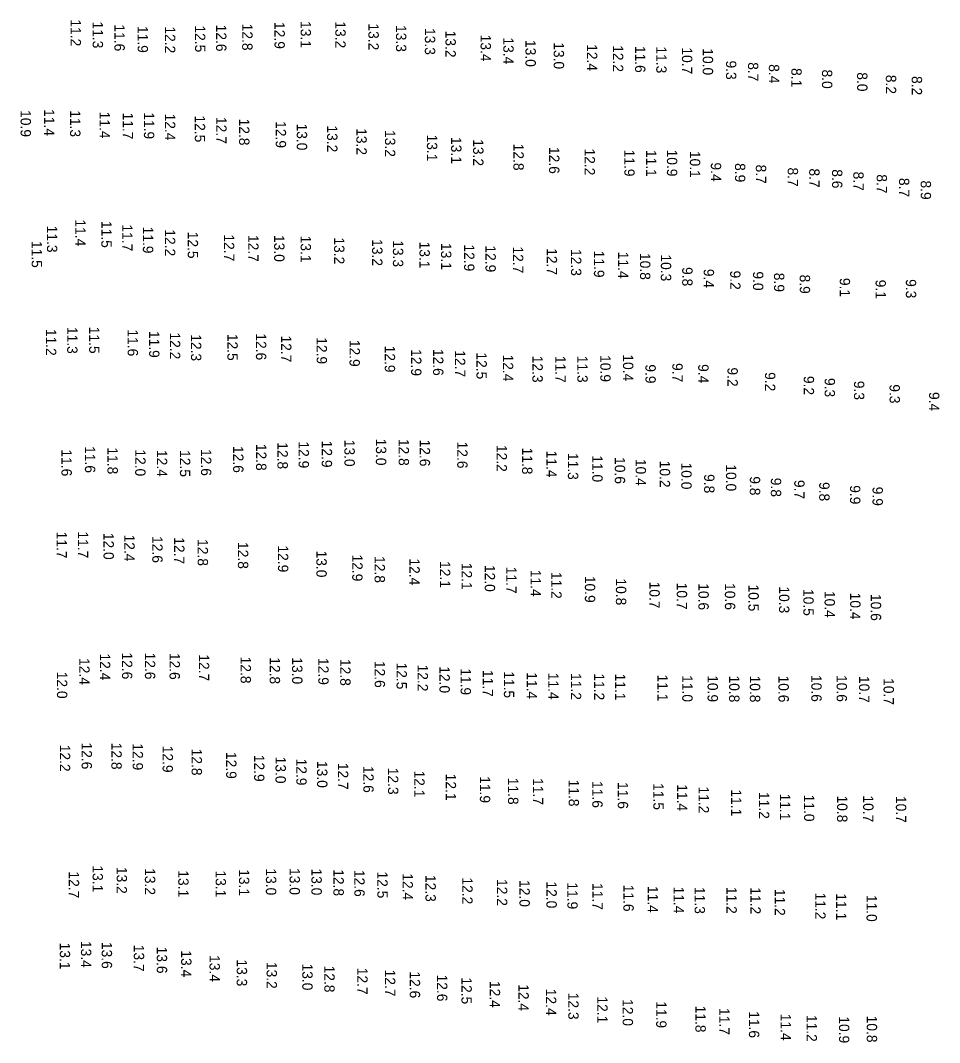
# Model space of a CAD drawing. Extents: x 988130 to 1132882, y 654656 to 841453.
# Drawn here: x 1112009.9 to 1112454.6, y 656908.8 to 657403.6 of the extents above; entities that cross this region are included whole.
import ezdxf

# ---------------------------------------------------------------- set-up
doc = ezdxf.new("R2010")
doc.units = 0
doc.layers.add('V-TOPO-SOUN', color=7, linetype='Continuous')

msp = doc.modelspace()

# ---------------------------------------------------------------- texts
at = {"layer": 'V-TOPO-SOUN'}
for s, p in [('11.2 ', (1112034.21, 657404.08)), ('11.3 ', (1112044.89, 657403.06)), ('11.6 ', (1112055.4, 657401.66)), ('11.9 ', (1112066.64, 657400.9)), ('12.5 ', (1112094.38, 657401.15)), ('12.6 ', (1112104.59, 657401.54)), ('12.8 ', (1112117.22, 657402)), ('12.9 ', (1112132.84, 657402.81)), ('13.1 ', (1112145.49, 657403.25)), ('13.2 ', (1112162.28, 657403.13)), ('13.2 ', (1112178.29, 657402.13)), ('13.3 ', (1112191.62, 657401.33)), ('12.2 ', (1112079.87, 657400.69)), ('13.3 ', (1112205.58, 657399.89)), ('13.2 ', (1112215.56, 657398.63)), ('13.4 ', (1112232.55, 657396.68)), ('13.4 ', (1112243.55, 657395.34)), ('13.0 ', (1112254.26, 657394.1)), ('13.0 ', (1112267.93, 657393.02)), ('12.4 ', (1112283.98, 657392.09)), ('12.2 ', (1112296.56, 657391.61)), ('11.6 ', (1112307.28, 657391.26)), ('11.3 ', (1112317.53, 657390.98)), ('10.7 ', (1112329.96, 657390.53)), ('10.0 ', (1112340.02, 657390.08)), ('9.3', (1112351.27, 657384.17)), ('8.7', (1112361.92, 657383.35)), ('8.4', (1112372.01, 657382.39)), ('8.1', (1112382.89, 657380.52)), ('8.0', (1112397.71, 657379.81)), ('8.0', (1112414.71, 657378.48)), ('8.2', (1112428.61, 657377.24)), ('8.2', (1112441.13, 657376.65)), ('10.9 ', (1112010.01, 657360.16)), ('11.4 ', (1112021.41, 657360.64)), ('11.3 ', (1112033.97, 657360.12)), ('11.4 ', (1112048.21, 657359.42)), ('11.7 ', (1112059.46, 657358.98)), ('11.9 ', (1112069.68, 657359.12)), ('12.4 ', (1112079.85, 657358.5)), ('12.5 ', (1112094.3, 657357.58)), ('12.7 ', (1112104.65, 657356.84)), ('12.8 ', (1112115.72, 657356.05)), ('12.9 ', (1112133.45, 657354.83)), ('13.0 ', (1112143.64, 657353.68)), ('13.2 ', (1112158.3, 657352.76)), ('13.2 ', (1112172.46, 657351.42)), ('13.2 ', (1112186.3, 657350.51)), ('13.1 ', (1112206.58, 657348.34)), ('13.1 ', (1112218.3, 657347.14)), ('13.2 ', (1112228.94, 657346.1)), ('12.8 ', (1112248.42, 657343.91)), ('12.6 ', (1112265.68, 657342.33)), ('12.2 ', (1112282.87, 657341.58)), ('11.9 ', (1112302.09, 657341.04)), ('11.1 ', (1112312.64, 657340.9)), ('10.9 ', (1112322.7, 657341.05)), ('10.1 ', (1112333.8, 657340.42)), ('9.4', (1112343.95, 657334.82)), ('8.9', (1112355.62, 657334.52)), ('8.7', (1112365.71, 657333.79)), ('8.7', (1112381.14, 657332.39)), ('8.7', (1112391.54, 657331.93)), ('8.6', (1112402.58, 657331.54)), ('8.7', (1112412.86, 657330.41)), ('8.7', (1112424.18, 657329.1)), ('8.7', (1112434.96, 657327.34)), ('8.9', (1112445.47, 657326.11)), ('11.4 ', (1112036.47, 657307.26)), ('11.3 ', (1112022.77, 657304.23)), ('11.5 ', (1112049.09, 657306.5)), ('11.7 ', (1112059.15, 657304.83)), ('11.9 ', (1112069.17, 657303.77)), ('12.2 ', (1112079.83, 657302.46)), ('12.5 ', (1112090.88, 657301.3)), ('12.7 ', (1112108.39, 657300)), ('12.7 ', (1112120.11, 657299.74)), ('13.0 ', (1112132.67, 657299.72)), ('13.1 ', (1112145.49, 657299.41)), ('13.2 ', (1112161.67, 657298.55)), ('13.2 ', (1112180.08, 657297.71)), ('13.3 ', (1112190.13, 657297.2)), ('11.5 ', (1112015.36, 657296.86)), ('13.1 ', (1112202.98, 657296.53)), ('13.1 ', (1112213.42, 657295.84)), ('12.9 ', (1112224.55, 657295.16)), ('12.9 ', (1112234.91, 657294.69)), ('12.7 ', (1112248.21, 657294.17)), ('12.7 ', (1112264.55, 657293.32)), ('12.3 ', (1112276.3, 657292.91)), ('11.9 ', (1112287.38, 657292.12)), ('11.4 ', (1112299.06, 657291.63)), ('10.8 ', (1112309.68, 657291)), ('10.3 ', (1112319.75, 657290.33)), ('9.8', (1112330.1, 657284.19)), ('9.4', (1112340.5, 657283.34)), ('9.2', (1112353.29, 657282.5)), ('9.0', (1112364.34, 657282.1)), ('8.9', (1112374.5, 657281.43)), ('8.9', (1112386.96, 657280.54)), ('9.1', (1112406.3, 657278.95)), ('9.1', (1112423.63, 657278.09)), ('9.3', (1112438.28, 657278.34)), ('11.2 ', (1112022.27, 657254.29)), ('11.3 ', (1112032.54, 657255.22)), ('11.5 ', (1112043.18, 657255.3)), ('11.6 ', (1112061.82, 657254.01)), ('11.9 ', (1112072.18, 657253.29)), ('12.2 ', (1112082.25, 657252.54)), ('12.3 ', (1112092.45, 657251.67)), ('12.5 ', (1112110.05, 657251.86)), ('12.6 ', (1112123.86, 657252.11)), ('12.7 ', (1112136.03, 657251.07)), ('12.9 ', (1112153.24, 657250.23)), ('12.9 ', (1112169.14, 657248.97)), ('12.9 ', (1112186.19, 657246.17)), ('12.9 ', (1112198.94, 657244.47)), ('12.6 ', (1112209.56, 657244.59)), ('12.7 ', (1112220.17, 657243.92)), ('12.5 ', (1112230.56, 657242.89)), ('12.4 ', (1112243.33, 657241.85)), ('12.3 ', (1112257.62, 657241.29)), ('11.7 ', (1112268.72, 657241.23)), ('11.3 ', (1112279.37, 657241.25)), ('10.9 ', (1112290.47, 657241.58)), ('10.4 ', (1112301.44, 657241.94)), ('9.7', (1112325.32, 657237.73)), ('9.9', (1112312.3, 657237.12)), ('9.4', (1112337.84, 657237.22)), ('9.2', (1112351.99, 657235.6)), ('9.2', (1112370.14, 657233.34)), ('9.2', (1112388.88, 657231.51)), ('9.3', (1112399.01, 657230.52)), ('9.3', (1112413.19, 657229.13)), ('9.3', (1112430.4, 657227.45)), ('9.4', (1112449.51, 657223.71)), ('12.8 ', (1112123.94, 657198.63)), ('12.8 ', (1112134.29, 657199.38)), ('12.9 ', (1112144.51, 657199.8)), ('12.9 ', (1112155.7, 657200.16)), ('13.0 ', (1112166.68, 657200.61)), ('13.0 ', (1112181.91, 657201.15)), ('12.8 ', (1112192.92, 657201.02)), ('12.6 ', (1112203.1, 657200.7)), ('12.6 ', (1112221.23, 657199.71)), ('12.2 ', (1112240.3, 657198.1)), ('11.6 ', (1112029.78, 657195.92)), ('11.6 ', (1112041.13, 657197.52)), ('11.8 ', (1112052.05, 657196.89)), ('12.0 ', (1112065.45, 657195.95)), ('12.4 ', (1112075.92, 657195.65)), ('12.5 ', (1112087.09, 657195.6)), ('12.6 ', (1112097.3, 657196.11)), ('12.6 ', (1112112.83, 657197.6)), ('11.8 ', (1112252.63, 657196.82)), ('11.4 ', (1112264.42, 657195.32)), ('11.3 ', (1112274.78, 657194.24)), ('11.0 ', (1112286.57, 657193.11)), ('10.6 ', (1112297.48, 657192.21)), ('10.4 ', (1112307.56, 657191.34)), ('10.2 ', (1112319.22, 657190.47)), ('10.0 ', (1112329.65, 657189.57)), ('10.0 ', (1112351.25, 657188.71)), ('9.8', (1112340.7, 657183.98)), ('9.8', (1112362.81, 657182.92)), ('9.8', (1112372.98, 657182.19)), ('9.7', (1112384.3, 657181.17)), ('9.8', (1112396.37, 657180.15)), ('9.9', (1112411.27, 657178.61)), ('9.9', (1112422.17, 657177.89)), ('11.7 ', (1112027.41, 657156.13)), ('11.7 ', (1112037.71, 657156.26)), ('12.0 ', (1112050.11, 657155.56)), ('12.4 ', (1112060.21, 657154.71)), ('12.6 ', (1112073.71, 657153.98)), ('12.7 ', (1112084.28, 657153.41)), ('12.8 ', (1112095.69, 657152.51)), ('12.8 ', (1112115.15, 657151.1)), ('12.9 ', (1112134.52, 657149.45)), ('13.0 ', (1112153.11, 657146.98)), ('12.9 ', (1112170.45, 657145.06)), ('12.8 ', (1112181.27, 657144.29)), ('12.4 ', (1112198.12, 657143.17)), ('12.1 ', (1112212.89, 657141.89)), ('12.1 ', (1112223.4, 657141.03)), ('12.0 ', (1112234.55, 657140.02)), ('11.7 ', (1112244.94, 657139.15)), ('11.4 ', (1112256.75, 657137.66)), ('11.2 ', (1112266.74, 657136.65)), ('10.9 ', (1112283, 657134.73)), ('10.8 ', (1112298.02, 657133.48)), ('10.7 ', (1112314.22, 657131.94)), ('10.7 ', (1112327.47, 657131.42)), ('10.6 ', (1112337.93, 657131.15)), ('10.6 ', (1112350.74, 657131.21)), ('10.5 ', (1112362.13, 657130.54)), ('10.3 ', (1112376.94, 657129.63)), ('10.5 ', (1112388.7, 657128.36)), ('10.4 ', (1112398.97, 657127.44)), ('10.4 ', (1112411.34, 657126.58)), ('10.6 ', (1112421.33, 657125.97)), ('12.4 ', (1112038.38, 657094.94)), ('12.4 ', (1112048.38, 657097.16)), ('12.6 ', (1112059.07, 657097.63)), ('12.6 ', (1112070.15, 657097.59)), ('12.6 ', (1112082.06, 657097.46)), ('12.7 ', (1112096.26, 657096.75)), ('12.8 ', (1112116.45, 657095.62)), ('12.8 ', (1112130.53, 657095.33)), ('13.0 ', (1112141.36, 657095.29)), ('12.9 ', (1112154.03, 657094.96)), ('12.8 ', (1112164.63, 657094.5)), ('12.6 ', (1112181.31, 657093.57)), ('12.5 ', (1112191.88, 657092.77)), ('12.2 ', (1112202.09, 657091.79)), ('12.0 ', (1112212.65, 657090.99)), ('11.9 ', (1112222.88, 657090.01)), ('11.7 ', (1112233.6, 657089.2)), ('12.0 ', (1112027.6, 657088.32)), ('11.5 ', (1112243.81, 657088.56)), ('11.4 ', (1112254.89, 657088.07)), ('11.4 ', (1112265.26, 657087.84)), ('11.2 ', (1112276.24, 657087.68)), ('11.2 ', (1112287.44, 657087.52)), ('11.1 ', (1112297.62, 657087.42)), ('11.1 ', (1112318.13, 657086.98)), ('11.0 ', (1112330.11, 657086.67)), ('10.9 ', (1112342.36, 657086.64)), ('10.8 ', (1112352.79, 657086.49)), ('10.8 ', (1112362.82, 657086.46)), ('10.6 ', (1112376.67, 657086.47)), ('10.6 ', (1112392.53, 657086.74)), ('10.6 ', (1112404.8, 657086.72)), ('10.7 ', (1112415.64, 657086.27)), ('10.7 ', (1112427.51, 657085.22)), ('12.2 ', (1112029, 657052.98)), ('12.6 ', (1112039.52, 657054.07)), ('12.8 ', (1112053.93, 657053.96)), ('12.9 ', (1112064.24, 657053.66)), ('12.9 ', (1112078.7, 657052.51)), ('12.8 ', (1112092.75, 657051.08)), ('12.9 ', (1112109.45, 657049.49)), ('12.9 ', (1112122.97, 657048.11)), ('13.0 ', (1112133.33, 657047.21)), ('12.9 ', (1112143.41, 657046.27)), ('13.0 ', (1112153.44, 657045.11)), ('12.7 ', (1112163.53, 657044.23)), ('12.6 ', (1112175.81, 657042.72)), ('12.3 ', (1112187.75, 657041.83)), ('12.1 ', (1112200.46, 657040.5)), ('12.1 ', (1112215.68, 657038.97)), ('11.9 ', (1112232.21, 657037.77)), ('11.8 ', (1112245.82, 657036.99)), ('11.7 ', (1112257.87, 657036.82)), ('11.8 ', (1112275.16, 657036.1)), ('11.6 ', (1112286.58, 657035.4)), ('11.6 ', (1112298.92, 657034.92)), ('11.5 ', (1112316.13, 657034.39)), ('11.4 ', (1112327.62, 657033.83)), ('11.2 ', (1112338.04, 657032.78)), ('11.1 ', (1112353.75, 657031.35)), ('11.2 ', (1112367.21, 657030.1)), ('11.1 ', (1112377.34, 657029.36)), ('11.0 ', (1112389.02, 657028.83)), ('10.8 ', (1112405.01, 657028.4)), ('10.7 ', (1112417.63, 657028.45)), ('10.7 ', (1112433.47, 657028.19)), ('12.7 ', (1112033.34, 656991.65)), ('13.1 ', (1112044.83, 656994.57)), ('13.2 ', (1112056.49, 656993.84)), ('13.2 ', (1112070.14, 656993.24)), ('13.1 ', (1112086.27, 656992.19)), ('13.1 ', (1112104.37, 656992.12)), ('13.1 ', (1112115.66, 656992.74)), ('13.0 ', (1112128.69, 656993.12)), ('13.0 ', (1112140.12, 656993.28)), ('13.0 ', (1112150.72, 656993.08)), ('12.8 ', (1112161.37, 656992.73)), ('12.6 ', (1112171.47, 656992.4)), ('12.5 ', (1112182.6, 656991.63)), ('12.4 ', (1112194.8, 656990.76)), ('12.3 ', (1112205.89, 656989.97)), ('12.2 ', (1112223.68, 656988.75)), ('12.2 ', (1112240.48, 656987.96)), ('12.0 ', (1112251.35, 656987.47)), ('12.0 ', (1112264.4, 656986.81)), ('11.9 ', (1112274.53, 656986.36)), ('11.7 ', (1112286.67, 656986.03)), ('11.6 ', (1112301.64, 656985.23)), ('11.4 ', (1112313.41, 656984.62)), ('11.4 ', (1112325.91, 656984.35)), ('11.3 ', (1112336.11, 656984.12)), ('11.2 ', (1112351.49, 656984.18)), ('11.2 ', (1112363.07, 656983.96)), ('11.2 ', (1112374.86, 656983.22)), ('11.2 ', (1112394.45, 656981.45)), ('11.1 ', (1112404.55, 656981.05)), ('11.0 ', (1112419.26, 656980.32)), ('13.1 ', (1112028.98, 656957.2)), ('13.4 ', (1112039.21, 656957.99)), ('13.6 ', (1112049.27, 656957.55)), ('13.7 ', (1112064.79, 656956.16)), ('13.6 ', (1112075.9, 656955.23)), ('13.4 ', (1112087.68, 656953.45)), ('13.4 ', (1112101.4, 656951.15)), ('13.3 ', (1112114.59, 656949.05)), ('13.2 ', (1112129.02, 656947.87)), ('13.0 ', (1112146.28, 656947.08)), ('12.8 ', (1112156.96, 656946.08)), ('12.7 ', (1112172.89, 656945.02)), ('12.7 ', (1112186.32, 656944.13)), ('12.6 ', (1112198.29, 656943.28)), ('12.6 ', (1112211.47, 656941.74)), ('12.5 ', (1112223.29, 656940.37)), ('12.4 ', (1112237.01, 656938.63)), ('12.4 ', (1112250.86, 656937.08)), ('12.4 ', (1112264.14, 656934.87)), ('12.3 ', (1112274.97, 656932.93)), ('12.1 ', (1112288.98, 656931.16)), ('12.0 ', (1112301.3, 656929.84)), ('11.9 ', (1112317.49, 656928.82)), ('11.8 ', (1112336.47, 656926.7)), ('11.7 ', (1112348.02, 656925.54)), ('11.6 ', (1112362.37, 656924.02)), ('11.4 ', (1112377.73, 656922.77)), ('11.2 ', (1112390.26, 656922.22)), ('10.9 ', (1112405.94, 656921.52)), ('10.8 ', (1112419.37, 656921.84))]:
    msp.add_text(s, height=5, rotation=270, dxfattribs=at).set_placement(p)

doc.saveas('drawing.dxf')
